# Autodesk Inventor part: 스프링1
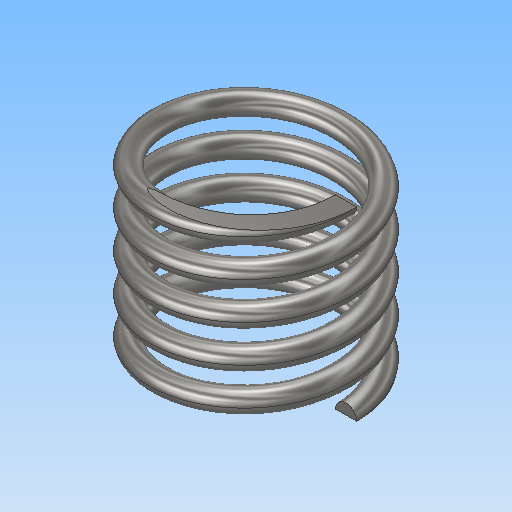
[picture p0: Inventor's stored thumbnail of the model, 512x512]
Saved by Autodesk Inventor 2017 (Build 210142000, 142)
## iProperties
Part Number: 스프링1
Material: 스테인레스 스틸
Document SubType Name: Modeling
Designer: MRC
Density: 8 g/cm^3
Appearance: 반연마
Mass: 6.54895 g
Surface Area: 16.6959 cm^2
Volume: 0.818619 cm^3
Author: MRC
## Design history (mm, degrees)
sketch "스케치1"
  geometry: L1 (0, 0)-(0, 17.5); L2 (0, 0)-(8.5, 0); L3 (0, 17.5)-(8.5, 17.5); C1 r 1 at (8.5, 0)
  constraints: 6 end point, 2 horizontal, 1 centre point, 1 coincident, 1 parallel, 1 vertical
  dimensions: "d0" = 17.5 distance of L1.start L1.end (derived); "d1" = 2 diameter of C1; "d2" = 17 diameter of L2.end L1
feature "코일1" sketch "스케치1" pitch "d3" = 10; turns "d5" = 5; dims "d4" = 17.5 (= d0), "d6" = 0, angle "d7" = 90 deg, angle "d8" = 90 deg, "d9" = 0, "d10" = 0
sketch "스케치2"
  geometry: L1 (17.5, 10)-(0, 10); L2 (0, 10)-(0, -10); L3 (0, -10)-(17.5, -10); L4 (17.5, -10)-(17.5, 10); 2 further points
  constraints: 8 end point, 2 parallel, 1 coincident, 1 horizontal, 1 midpoint, 1 perpendicular
  dimensions: "d11" = 17.5 distance of L2.end L3.end (= d0); "d12" = 20 distance of L3.end L1.start
extrude "돌출1" sketch "스케치2" stored distance "d13" = 0; taper "d14" = 0 deg
node "솔리드1"
